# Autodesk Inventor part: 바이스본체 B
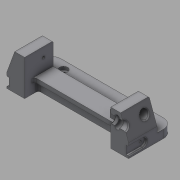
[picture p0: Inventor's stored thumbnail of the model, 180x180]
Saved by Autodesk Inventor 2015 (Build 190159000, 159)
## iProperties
Created: 2017-04
Part Number: 바이스본체 B
Material: 알루미늄 6061
Document SubType Name: Modeling
Designer: mduedu
Density: 2.71 g/cm^3
Mass: 324.158 g
Surface Area: 275.767 cm^2
Volume: 119.615 cm^3
Appearance: 기본값
Author: mduedu
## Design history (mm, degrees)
sketch "스케치1"
  geometry: L1 (-75, 0)-(75, 0); L2 (-75, 0)-(-75, 17); L3 (-53, 17)-(53, 17); L4 (75, 17)-(75, 0); L5 (-75, 17)-(-65.173, 44); L6 (-65.173, 44)-(-53, 44); L7 (-53, 44)-(-53, 17); L8 (0, 0)-(0, 17); L9 (75, 17)-(65.173, 44); L10 (65.173, 44)-(53, 44); L11 (53, 44)-(53, 17); 1 further point
  constraints: 22 end point, 4 perpendicular, 2 horizontal alignment, 2 midpoint, 2 symmetric about line, 1 coincident, 1 collinear, 1 horizontal, 1 vertical
  dimensions: "d0" = 150 distance of L1.start L1.end; "d1" = 17 distance of L1.start L2.end; "d2" = 27 distance of L3.start L6.end; "d3" = 22 distance of L3.start L2.end; "d4" = 70 deg angle of L3 L5; "d54" = 20 deg angle of L9 L4
extrude "돌출1" new body sketch "스케치1" stored distance "d5" = 70; taper "d6" = 0 deg
sketch "스케치2"
  geometry: L1 (0, 70)-(106, 70) reference; L2 (106, 70)-(106, 0) reference; L3 (106, 0)-(0, 0) reference; L4 (0, 47)-(106, 47); L5 (106, 47)-(106, 23); L6 (106, 23)-(0, 23); L7 (0, 23)-(0, 47); L8 (0, 70)-(0, 0) reference; 2 further points
  constraints: 8 end point, 2 parallel, 2 point on line, 1 horizontal, 1 horizontal alignment, 1 midpoint, 1 perpendicular
  dimensions: "d7" = 24 distance between parallel lines of L6 L4
extrude "돌출2" cut sketch "스케치2" stored distance "d9" = 70; taper "d10" = 0 deg
sketch "스케치3"
  geometry: L1 (22, -23)-(128, -23) reference; L2 (128, -47)-(22, -47) reference; L3 (22, -18)-(128, -18); L4 (128, -52)-(22, -52); L5 (22, -18)-(22, -52); L6 (128, -18)-(128, -52); 1 further point
  constraints: 8 end point, 3 parallel, 2 point on line, 1 perpendicular
  dimensions: "d11" = 5 distance between parallel lines of L3 L1; "d12" = 5 distance between parallel lines of L4 L2
extrude "돌출3" cut sketch "스케치3" distance "d13" = 12; taper "d14" = 0 deg
fillet "모깎기1" dims "d15" = 3, "d16" = 3
sketch "스케치4"
  geometry: L1 (103, 23)-(3, 23) reference; L2 (0, 26)-(0, 0) reference; L3 (106, 0)-(0, 0) reference; L4 (106, 26)-(106, 0) reference; L5 (96, 0)-(90, 0); L6 (90, 0)-(90, 19.5); L7 (96, 19.5)-(96, 0); L8 (90, 19.5)-(96, 19.5); A1 r 3 centre (3, 26) between (0, 26) and (3, 23) reference; A2 r 3 centre (103, 26) between (103, 23) and (106, 26) reference; 1 further point
  constraints: 8 end point, 2 perpendicular, 1 horizontal, 1 parallel, 1 point on line
  dimensions: "d17" = 10 distance between parallel lines of L7 L4; "d18" = 6 distance between parallel lines of L7 L6; "d27" = 3.5 distance between parallel lines of L8 L1
extrude "돌출4" join sketch "스케치4" distance "d19" = 12; taper "d20" = 0 deg
chamfer "모따기1" distance "d21" = 3; stored, may be unused: second distance "d22" = 2, angle "d23" = 45 deg
chamfer "모따기2" distance "d24" = 3; stored, may be unused: second distance "d25" = 2, angle "d26" = 45 deg
sketch "스케치5"
  geometry: L1 (-15.5, 35.8)-(-15.5, -25.8) reference; L2 (19.5, 0)-(0, 0) reference; C1 r 6.5 at (9.5, 15); 1 further point
  constraints: 1 centre point
  dimensions: "d28" = 13 diameter of C1; "d30" = 15 distance from line of C1.centre L2; "d31" = 25 distance from line of C1.centre L1
extrude "돌출5" cut sketch "스케치5" stored distance "d32" = 12; taper "d33" = 0 deg
sketch "스케치6"
  geometry: C1 r 5 at (-10, 15); C2 r 5 at (-60, 15); A1 r 6.5 centre (-10, 15) between (-15.766, 12) and (-4.234, 12) reference; A2 r 6.5 centre (-60, 15) between (-65.766, 12) and (-54.234, 12) reference; 1 further point
  constraints: 2 centre point, 2 coincident
  dimensions: "d34" = 10 diameter of C1; "d35" = 10 diameter of C2 (= d34)
extrude "돌출6" cut sketch "스케치6" stored distance "d36" = 12; taper "d37" = 0 deg
chamfer "모따기3" distance "d38" = 1; stored, may be unused: second distance "d39" = 2, angle "d40" = 45 deg
chamfer "모따기4" distance "d41" = 1; stored, may be unused: second distance "d42" = 2, angle "d43" = 45 deg
sketch "스케치7"
  geometry: L1 (-35, 35.8)-(-35, -25.8) reference; L2 (-70, 0)-(0, 0) reference; C1 r 5 at (-35, 15); 1 further point
  constraints: 1 centre point, 1 point on line
  dimensions: "d44" = 10 diameter of C1; "d45" = 15 distance from line of C1.centre L2
extrude "돌출7" cut sketch "스케치7" stored distance "d46" = 12; taper "d47" = 0 deg
chamfer "모따기5" distance "d48" = 1; stored, may be unused: second distance "d49" = 2, angle "d50" = 45 deg
node "작업축1"
sketch "스케치8"
  geometry: L1 (-105, 32)-(105, 32) reference; L2 (58, 32)-(64, 32); L3 (64, 32)-(64, 40); L4 (64, 40)-(58, 40); L5 (58, 40)-(58, 32); L6 (53, 38)-(53, 26) reference; 1 further point
  constraints: 8 end point, 2 parallel, 1 horizontal, 1 perpendicular, 1 point on line
  dimensions: "d51" = 5 distance from line of L6 L2.start; "d52" = 6 distance of L3.end L4.end; "d53" = 16 diameter of L4 L1
revolve "회전1" sketch "스케치8" stored, may be unused: angle "d55" = 90 deg
fillet "모깎기2"
chamfer "모따기6" distance "d56" = 1; stored, may be unused: second distance "d57" = 2, angle "d58" = 45 deg
sketch "스케치9"
  geometry: L1 (17.5, 3)-(52.5, 3); L2 (52.5, 13)-(17.5, 13); L3 (70, 0)-(0, 0) reference; L4 (17.5, 8)-(52.5, 8); A1 r 5 centre (17.5, 8) between (17.5, 13) and (17.5, 3); A2 r 5 centre (52.5, 8) between (52.5, 3) and (52.5, 13); 3 further points
  constraints: 6 end point, 4 point on circle, 3 tangent, 2 centre point, 2 midpoint, 2 parallel, 1 horizontal, 1 vertical alignment
  dimensions: "d59" = 35 distance of L4.start L4.end; "d61" = 5 radius of A2; "d62" = 8 distance between parallel lines of L3 L4
extrude "돌출8" cut sketch "스케치9" distance "d63" = 3; taper "d64" = 0 deg
chamfer "모따기7" distance "d65" = 1; stored, may be unused: second distance "d66" = 2, angle "d67" = 45 deg
chamfer "모따기8" distance "d68" = 1; stored, may be unused: second distance "d69" = 2, angle "d70" = 45 deg
feature "분할1"
sketch "스케치10"
  geometry: A1 r 5 centre (0, 0) between (0, 5) and (0, -5) reference; 1 further point
  constraints: 1 coincident
hole "구멍1" sketch "스케치10" at (0, 0) diameter "d71" = 2.459; stored, may be unused: countersink angle "d75" = 90 deg, drill point angle "d77" = 120 deg; dims "d72" = 4.5, "d73" = 4, "d74" = 2, "d76" = 6
sketch "스케치11"
  geometry: L1 (0, 0)-(0, 27) reference; L2 (0, 27)-(-35, 27) reference; 2 further points
  dimensions: "d78" = 12 distance from line of point (-12, 15.5) L1; "d79" = 11.5 distance from line of point (-12, 15.5) L2
hole "구멍2" sketch "스케치11" at (-12, 15.5) diameter "d80" = 3.242; stored, may be unused: countersink angle "d84" = 90 deg, drill point angle "d86" = 120 deg; dims "d81" = 6, "d82" = 4, "d83" = 2, "d85" = 8
sketch "스케치12"
  geometry: L1 (-75, -35)-(-75, 0) reference; L2 (75, -35)-(75, 0) reference; L3 (75, -35)-(-75, -35); L4 (-75, -35)-(-75, -55); L5 (-75, -55)-(75, -55); L6 (75, -55)-(75, -35); 1 further point
  constraints: 8 end point, 2 parallel, 1 horizontal, 1 perpendicular, 1 point on line
  dimensions: "d87" = 20 distance of L3.end L4.end; "d89" = 150 distance of L4.end L5.end (derived)
extrude "돌출9" join sketch "스케치12" distance "d90" = 10; taper "d91" = 0 deg
sketch "스케치13"
  geometry: L1 (-75, 55)-(-75, 35) reference; L2 (75, 35)-(75, 55) reference; L3 (-75, 45)-(75, 45); 3 further points
  constraints: 2 end point, 2 midpoint, 2 point on line
  dimensions: "d92" = 50 horizontal distance of point (-50, 45) point (0, 0); "d93" = 100 distance of point (50, 45) point (-50, 45)
fillet "모깎기3" dims "d94" = 12
chamfer "모따기9" distance "d95" = 1; stored, may be unused: second distance "d96" = 2, angle "d97" = 45 deg
hole "구멍3" sketch "스케치13" diameter "d98" = 4.134; stored, may be unused: countersink angle "d102" = 90 deg, drill point angle "d104" = 118 deg; dims "d99" = 6, "d100" = 10, "d101" = 4, "d103" = 8
node "솔리드1"
mirror "대칭1"
mirror "대칭2"
mirror "대칭3"
mirror "대칭4"
node "투영된 루프1"
